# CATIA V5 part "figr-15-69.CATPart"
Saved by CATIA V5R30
Part number: Part1
Bounding box of the stored display mesh (mm): x -110.541 to 53, y 0 to 2, z -29.652 to 29.652
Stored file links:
  D:\PROJECTS\CATIA V56R 2020\Resources\Parts File\c15_catia_v5_6r2020_prt\figr-15-69.CATPart
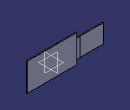
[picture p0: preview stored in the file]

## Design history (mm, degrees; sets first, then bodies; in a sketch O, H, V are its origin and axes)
SheetMetalParameters1: Thickness 2, BendRadius 4, KFactor 0.400515 {= log(min(100,max(20*SheetMetalParameters1.BendRadius,SheetMetalParameters1.Thickness)/SheetMetalParameters1.Thickness))/log(100)/2}, ReliefRadialLength 1, ReliefAxialLength 2, MinimumBendRadius 0
Body1 (main body)
  Sketch1 on zx-plane, origin (0, 0, 0), H (-1, 0, 0), V (0, 0, 1)
    line L1 (53, 29.6521) -> (53, -29.6521)
    line L2 (53, -29.6521) -> (-53, -29.6521)
    line L3 (-53, -29.6521) -> (-53, 29.6521)
    line L4 (-53, 29.6521) -> (53, 29.6521)
    vertical: L1 V, L3 V
    horizontal: L2 H, L4 H
    equidistance: L1 L3 O, L2 L4 O
  Wall1: Thickness 2, Profile Sketch1, OffsetValue 0
  Plane1: type Offset, RefPlane face of Wall1, Offset 10
  Plane2: type Offset, RefPlane face of Wall1, Offset 10
  Flange1: Angle 90, Length 50, Radius 4 {= SheetMetalParameters1.BendRadius}, KFacteur 0.400515 {= log(min(100,max(20*Flange1.Radius,SheetMetalParameters1.Thickness)/SheetMetalParameters1.Thickness))/log(100)/2}, Guide edge [face of Wall1 | face of Wall1], Limit1 Plane1, Limit2 Plane2
  Unfold1: FoldUnfold_Angles 90, FoldUnfold_FoldUnfoldFaces face of Flange1, FoldUnfold_ReferenceFaces face of Wall1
